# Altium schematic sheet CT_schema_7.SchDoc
size 146 x 119 mm
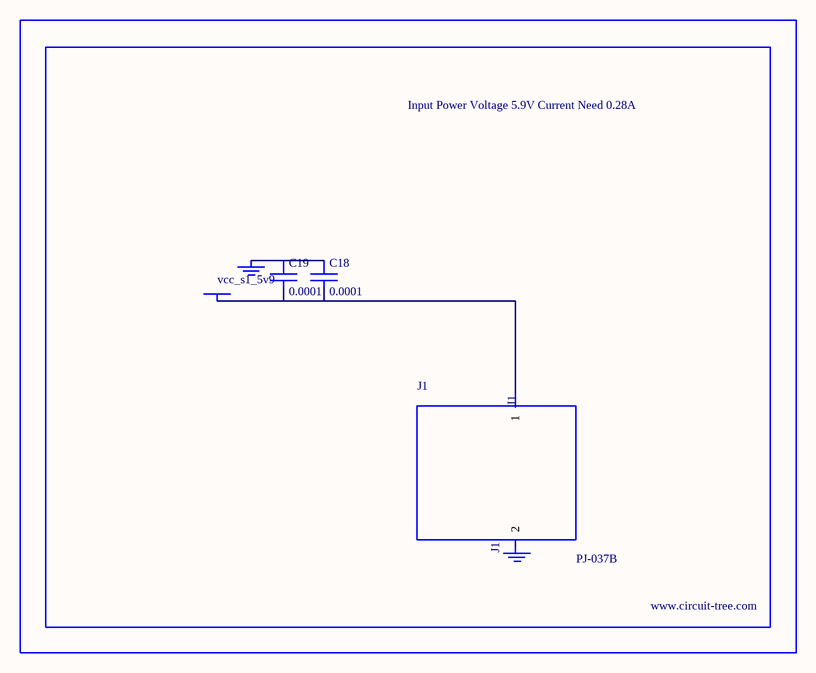
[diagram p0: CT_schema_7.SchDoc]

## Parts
BORDER6  (no value)
C18  0.0001  [EXV-9H]
C19  0.0001  [EXV-9H]
GND_INSTANCE_6_0  (no value)
GND_INSTANCE_6_1  (no value)
J1  PJ-037B  [PJ-037B_PACKAGE]
POWER_INSTANCE_6_0  vcc_s1_5v9

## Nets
NetC18_1: C18.1 C19.1 GND_INSTANCE_6_0.0(GND)
NetC18_2: C18.2 C19.2 J1.1 POWER_INSTANCE_6_0.0(PWR)

Not connected (* = marked no-connect by the designer): GND_INSTANCE_6_1 0(GND); J1 2

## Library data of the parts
BORDER6 = BORDER_PAGE6
C18 C19 = EDK107M035A9HAA
GND_INSTANCE_6_0 GND_INSTANCE_6_1 = GND
POWER_INSTANCE_6_0 = PWR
